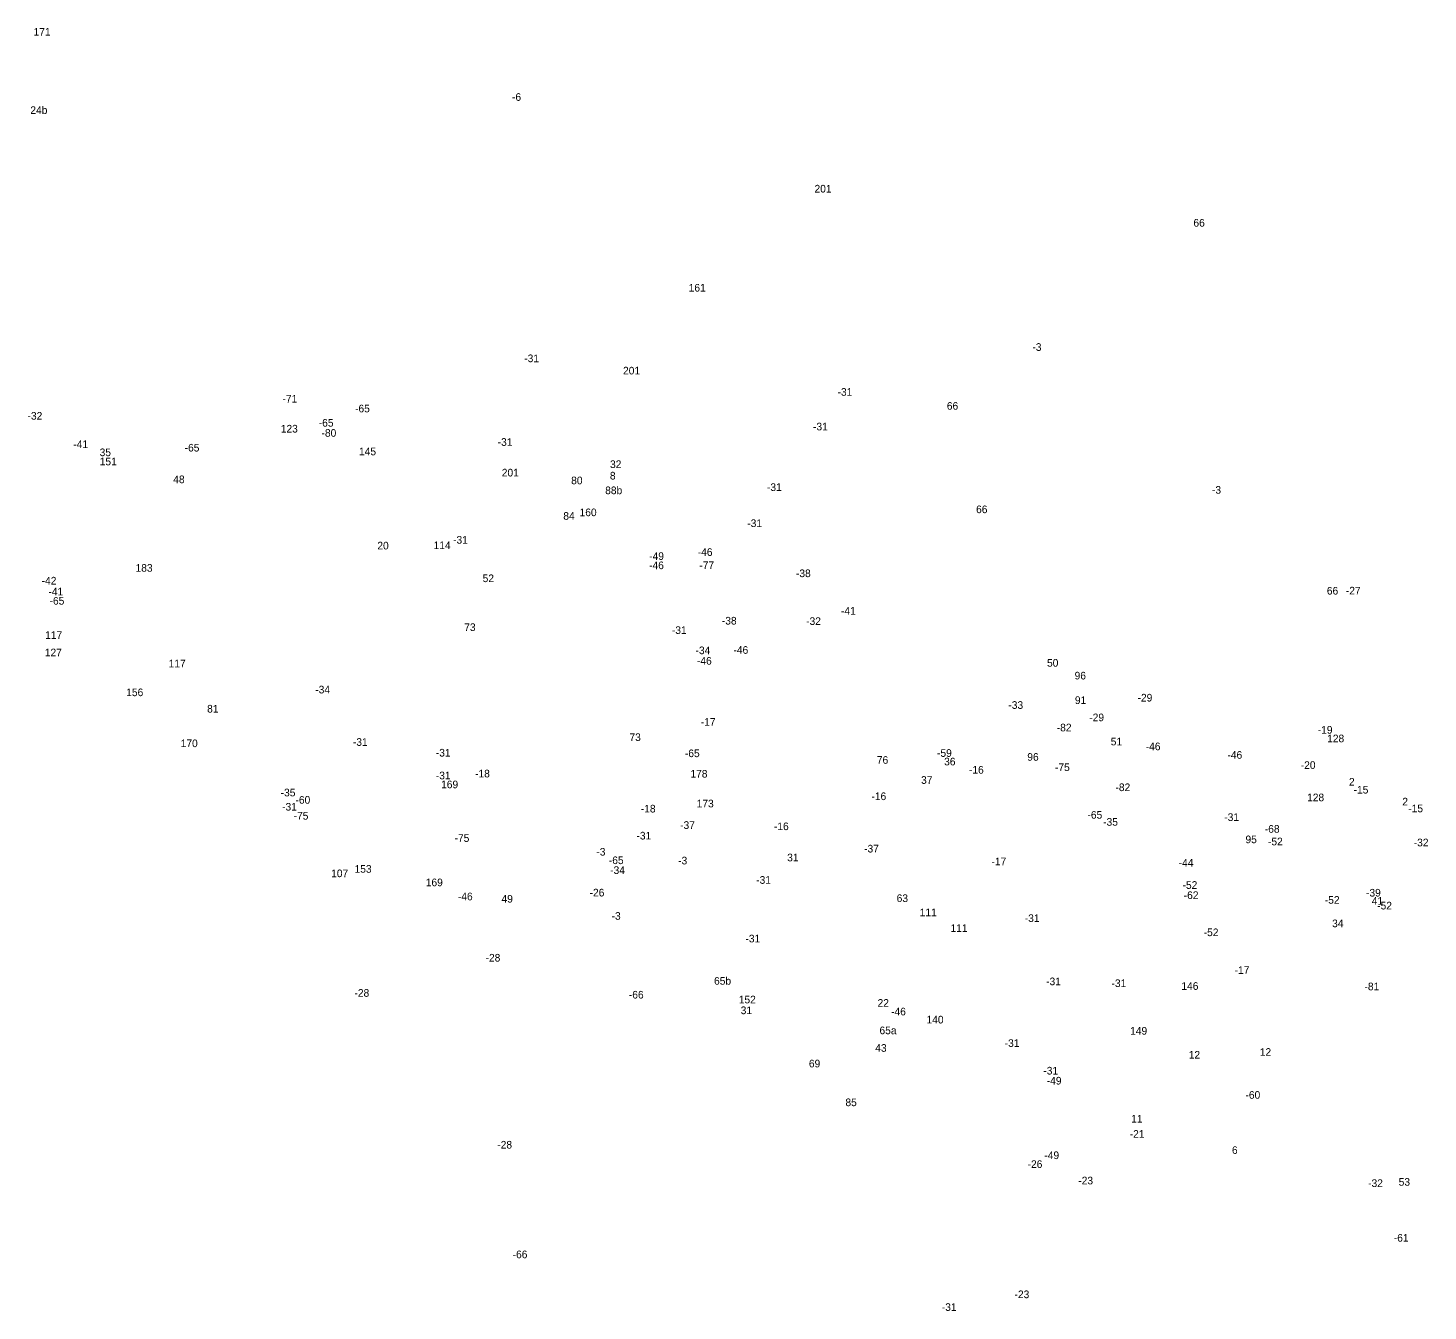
# Model space of a CAD drawing. Extents: x -664022 to -660357, y -995564 to -992665.
# Drawn here: x -662989 to -662256, y -994164 to -993493 of the extents above; entities that cross this region are included whole.
import ezdxf

# ---------------------------------------------------------------- set-up
doc = ezdxf.new("R2010")
doc.units = 0
doc.layers.add('Vrstva 24', color=7, linetype='Continuous')

msp = doc.modelspace()

# ---------------------------------------------------------------- texts
at = {"layer": 'Vrstva 24'}
for s, p in [('171', (-662986.002, -993496.87)), ('-6', (-662735.541, -993530.99)), ('24b', (-662987.698, -993537.86)), ('201', (-662577.216, -993578.97)), ('66', (-662378.869, -993596.83)), ('161', (-662643.082, -993630.82)), ('-3', (-662463.156, -993661.84)), ('-31', (-662729.15, -993667.77)), ('201', (-662677.446, -993674.19)), ('-71', (-662855.675, -993688.91)), ('-31', (-662565.15, -993685.34)), ('-65', (-662817.701, -993694.02)), ('66', (-662507.939, -993692.64)), ('-32', (-662989.156, -993697.85)), ('-65', (-662836.701, -993701.51)), ('-31', (-662577.98, -993703.45)), ('123', (-662856.592, -993704.58)), ('-80', (-662835.27, -993706.79)), ('-41', (-662965.214, -993712.71)), ('35', (-662951.428, -993716.96)), ('-65', (-662906.921, -993714.53)), ('145', (-662815.656, -993716.48)), ('-31', (-662743.05, -993711.54)), ('151', (-662951.386, -993721.75)), ('32', (-662684.248, -993723.17)), ('48', (-662912.882, -993731.09)), ('201', (-662740.906, -993727.58)), ('80', (-662704.592, -993731.67)), ('8', (-662684.318, -993729.17)), ('88b', (-662686.784, -993736.85)), ('-31', (-662602.1, -993735.17)), ('-3', (-662369.136, -993736.59)), ('66', (-662492.619, -993746.79)), ('84', (-662708.712, -993750.24)), ('160', (-662700.192, -993748.37)), ('-31', (-662612.41, -993754.05)), ('-31', (-662766.4, -993762.75)), ('20', (-662806.042, -993765.77)), ('114', (-662776.61, -993765.61)), ('-46', (-662638.326, -993769.15)), ('-46', (-662663.796, -993776.1)), ('-49', (-662663.746, -993771.28)), ('-77', (-662637.486, -993776.02)), ('-42', (-662981.77, -993784.13)), ('183', (-662932.632, -993777.44)), ('52', (-662750.928, -993782.88)), ('-38', (-662586.916, -993780.26)), ('-41', (-662978.224, -993789.83)), ('66', (-662309.009, -993789.4)), ('-27', (-662299.062, -993789.35)), ('-65', (-662977.631, -993794.66)), ('-38', (-662625.716, -993805.08)), ('-32', (-662581.576, -993805.28)), ('-32', (-662581.576, -993805.28)), ('-41', (-662563.354, -993799.93)), ('117', (-662979.942, -993812.57)), ('73', (-662760.554, -993808.48)), ('-31', (-662651.87, -993809.99)), ('-34', (-662639.5, -993820.59)), ('-46', (-662619.636, -993820.39)), ('127', (-662980.118, -993821.71)), ('117', (-662915.302, -993827.48)), ('-46', (-662638.746, -993826.07)), ('50', (-662455.502, -993827.14)), ('96', (-662441.059, -993833.81)), ('156', (-662937.498, -993842.56)), ('-34', (-662838.55, -993841.12)), ('-33', (-662475.736, -993849.2)), ('91', (-662440.908, -993846.65)), ('-29', (-662408.101, -993845.37)), ('81', (-662895.152, -993851.14)), ('-29', (-662433.391, -993855.68)), ('-17', (-662636.735, -993858.04)), ('-82', (-662450.396, -993860.98)), ('-19', (-662313.775, -993862.2)), ('170', (-662908.992, -993869.24)), ('-31', (-662818.85, -993868.56)), ('73', (-662674.084, -993866.02)), ('51', (-662422.162, -993868.3)), ('-46', (-662403.826, -993870.87)), ('128', (-662308.862, -993866.69)), ('-31', (-662775.44, -993874.16)), ('-65', (-662645.051, -993874.47)), ('76', (-662544.579, -993877.95)), ('-59', (-662513.081, -993874.32)), ('36', (-662509.364, -993878.79)), ('96', (-662465.829, -993876.37)), ('-46', (-662361.056, -993875.31)), ('-31', (-662775.44, -993886.08)), ('-18', (-662754.88, -993885.09)), ('178', (-662642.158, -993885.18)), ('-16', (-662496.355, -993883.11)), ('-75', (-662451.332, -993881.76)), ('-20', (-662322.68, -993880.64)), ('169', (-662772.683, -993890.76)), ('37', (-662521.434, -993888.45)), ('-82', (-662419.666, -993892.26)), ('2', (-662297.438, -993889.37)), ('-15', (-662295.01, -993893.52)), ('-35', (-662856.666, -993895.01)), ('-60', (-662848.885, -993898.84)), ('173', (-662638.898, -993900.76)), ('-16', (-662547.405, -993896.94)), ('128', (-662319.362, -993897.56)), ('2', (-662269.528, -993899.76)), ('-31', (-662855.89, -993902.44)), ('-75', (-662849.872, -993907.18)), ('-18', (-662668.13, -993903.44)), ('-65', (-662434.321, -993906.68)), ('-31', (-662362.72, -993907.88)), ('-15', (-662266.41, -993903.32)), ('-37', (-662647.552, -993912.03)), ('-16', (-662598.455, -993912.69)), ('-35', (-662426.116, -993910.38)), ('-68', (-662341.491, -993914.04)), ('-75', (-662765.622, -993918.82)), ('-31', (-662670.41, -993917.58)), ('95', (-662351.614, -993919.52)), ('-52', (-662339.836, -993920.63)), ('-32', (-662263.536, -993921.15)), ('-3', (-662691.406, -993926)), ('-65', (-662684.871, -993930.45)), ('-3', (-662648.586, -993930.62)), ('31', (-662591.512, -993928.99)), ('-37', (-662551.242, -993924.37)), ('-17', (-662484.555, -993931.09)), ('107', (-662830.232, -993937.3)), ('153', (-662817.982, -993934.98)), ('-34', (-662684.17, -993935.6)), ('-34', (-662684.17, -993935.6)), ('-44', (-662386.574, -993931.76)), ('169', (-662780.703, -993942.04)), ('-31', (-662607.73, -993940.76)), ('-52', (-662384.556, -993943.41)), ('-46', (-662763.886, -993949.4)), ('49', (-662741.058, -993950.61)), ('-26', (-662694.941, -993947.38)), ('63', (-662534.214, -993950.29)), ('-62', (-662383.951, -993948.74)), ('-52', (-662310.096, -993951.21)), ('-39', (-662288.521, -993947.44)), ('41', (-662285.526, -993951.73)), ('-3', (-662683.426, -993959.59)), ('111', (-662522.16, -993957.75)), ('-52', (-662282.676, -993954.18)), ('111', (-662506, -993965.94)), ('-31', (-662467.14, -993960.75)), ('34', (-662306.272, -993963.49)), ('-31', (-662613.37, -993971.43)), ('-52', (-662373.476, -993968.16)), ('-28', (-662749.396, -993981.46)), ('-17', (-662357.315, -993987.94)), ('65b', (-662629.808, -993993.58)), ('-31', (-662455.96, -993993.84)), ('-31', (-662421.73, -993994.81)), ('146', (-662385.172, -993996.27)), ('-81', (-662289.3, -993996.48)), ('-28', (-662818.026, -993999.89)), ('-66', (-662674.386, -994000.82)), ('152', (-662616.862, -994003.35)), ('31', (-662615.852, -994008.99)), ('22', (-662544.218, -994005.13)), ('-46', (-662537.116, -994009.62)), ('140', (-662518.58, -994013.86)), ('65a', (-662543.188, -994019.49)), ('-31', (-662477.67, -994026.14)), ('149', (-662412.012, -994019.74)), ('43', (-662545.412, -994028.68)), ('12', (-662381.322, -994032.27)), ('12', (-662344.122, -994030.8)), ('69', (-662580.149, -994036.85)), ('-31', (-662457.43, -994040.58)), ('-49', (-662455.636, -994045.82)), ('-60', (-662351.615, -994053.26)), ('85', (-662561.018, -994057.14)), ('11', (-662411.416, -994065.7)), ('-21', (-662412.2, -994073.67)), ('-28', (-662743.266, -994079.33)), ('-49', (-662456.896, -994084.84)), ('6', (-662358.704, -994082.15)), ('-26', (-662465.661, -994089.48)), ('-23', (-662439.126, -994098.08)), ('-32', (-662287.406, -994099.45)), ('53', (-662271.428, -994098.78)), ('-61', (-662273.965, -994128.05)), ('-61', (-662273.965, -994128.05)), ('-66', (-662735.226, -994136.73)), ('-23', (-662472.516, -994157.63)), ('-31', (-662510.57, -994164.29))]:
    msp.add_text(s, height=4, dxfattribs=at).set_placement(p)

doc.saveas('drawing.dxf')
